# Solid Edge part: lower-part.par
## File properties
Author: Vicky Raina
Template: Part8.par
Last saved by: MYPC
Revision: 6
Application: Solid Edge
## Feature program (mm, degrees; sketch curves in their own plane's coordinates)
body "unnamed Body 1"
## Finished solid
Body 1: solid body, 47 faces, 113 edges, 68 vertices.
  Faces by surface: plane 32, torus 8, cylinder 6, cone 1
  Edges by curve: circle 49, line 49, intersection 15
Bounding box of the edges (mm; curved faces can reach further): 68.011 x 85.812 x 6.000, from (-34.0057, -34, -6) to (34.0057, 51.8118, 0).
Cylindrical faces by radius (mm): R2.5 x2, R3 x1, R4.5 x2, R8 x1
Conical faces (half-angle, radius in mm at the cone's reference point): 45 deg R8 x1
Toroidal faces (ring radius, tube radius in mm): R18 r4 x1, R18 r6 x1, R28 r4 x1, R28 r6 x1, R60.4976 r4 x2, R60.4976 r6 x2
Planar faces by outward normal: +x 5, +y 4, +z 11, -x 4, -y 5, -z 3
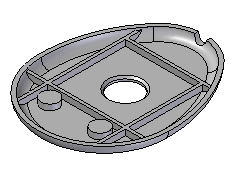
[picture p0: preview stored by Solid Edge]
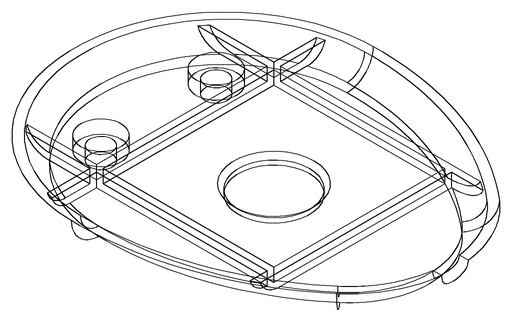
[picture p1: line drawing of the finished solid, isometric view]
